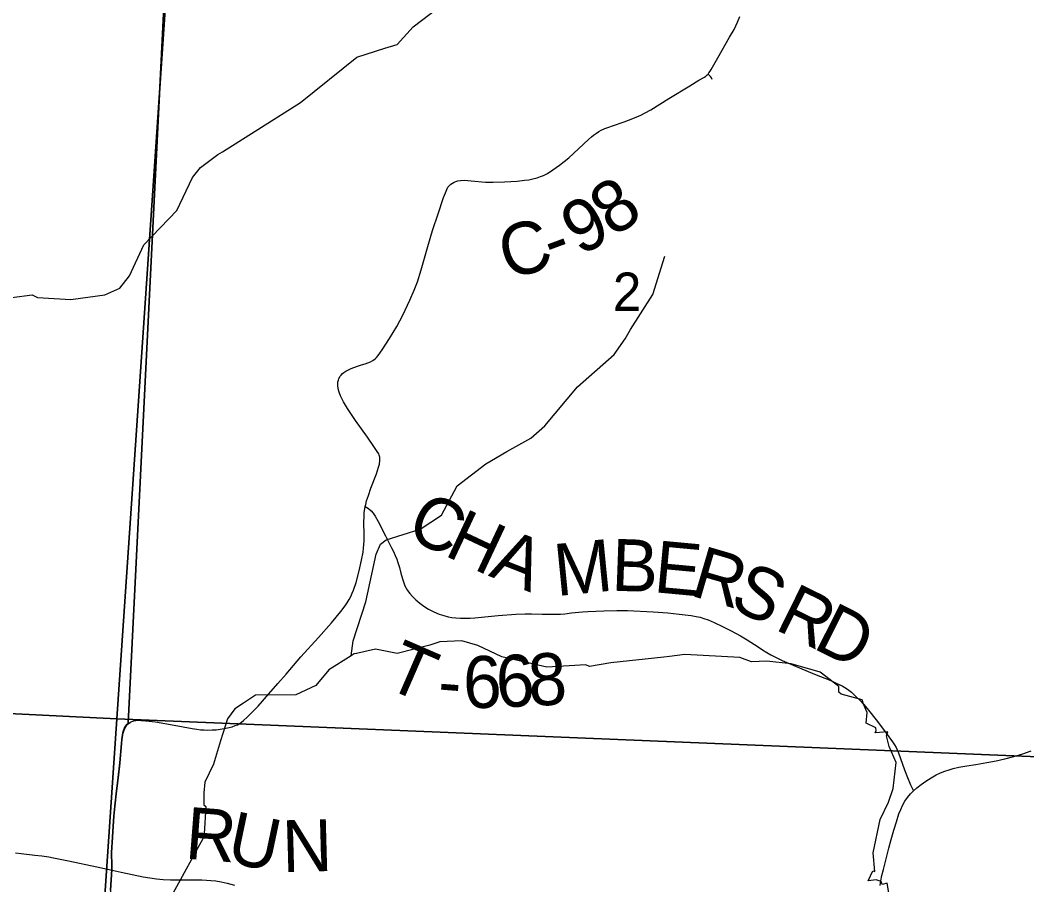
# Model space of a CAD drawing. Extents: x 396.2 to 468.4, y 232.6 to 279.1.
# Drawn here: x 420.393 to 421.493, y 271.098 to 272.044 of the extents above; entities that cross this region are included whole.
import ezdxf

# ---------------------------------------------------------------- set-up
doc = ezdxf.new("R2010")
doc.units = 0
for name, color, linetype in [('GM_X_County_Road', 7, 'Continuous'), ('GM_X_County_Road_Text', 7, 'Continuous'), ('GM_X_Minor_River', 7, 'Continuous'), ('GM_X_Section', 7, 'Continuous'), ('GM_X_Section_Text', 7, 'Continuous'), ('GM_X_Township', 7, 'Continuous'), ('GM_X_Township_Road', 7, 'Continuous'), ('GM_X_Township_Road_Text', 7, 'Continuous')]:
    doc.layers.add(name, color=color, linetype=linetype)

msp = doc.modelspace()

# ---------------------------------------------------------------- linework, layer by layer
at = {"layer": 'GM_X_County_Road'}
for points in [[(420.511, 271.2746), (420.512, 271.2754), (420.5135, 271.2763), (420.515, 271.2771), (420.517, 271.2777), (420.5195, 271.2781), (420.522, 271.2784), (420.5253, 271.2783), (420.5301, 271.2779), (420.5407, 271.2766), (420.5612, 271.273), (420.5809, 271.2693), (420.5859, 271.2686), (420.59, 271.2681), (420.5942, 271.2678), (420.5981, 271.2677), (420.6027, 271.2678), (420.6073, 271.2681), (420.6116, 271.2686), (420.616, 271.2693), (420.6214, 271.2705), (420.6245, 271.2713), (420.628, 271.2726), (420.6303, 271.2735), (420.6322, 271.2745), (420.6348, 271.2762), (420.6372, 271.278), (420.6409, 271.2817), (420.6529, 271.294), (420.6649, 271.3072), (420.6746, 271.3185), (420.6835, 271.3287), (420.6997, 271.3476), (420.719, 271.3688), (420.7334, 271.3851), (420.7435, 271.3974), (420.7481, 271.4035), (420.7505, 271.4068), (420.7526, 271.4105), (420.7544, 271.4138), (420.7559, 271.4173), (420.7573, 271.4206), (420.7601, 271.4289), (420.7636, 271.4419), (420.7661, 271.4533), (420.7678, 271.4623), (420.7684, 271.4666), (420.7687, 271.4706), (420.7688, 271.4747), (420.7689, 271.4822), (420.7687, 271.4944), (420.7689, 271.5019), (420.7691, 271.5055), (420.7696, 271.5097), (420.7702, 271.5122), (420.7706, 271.5145), (420.7716, 271.5183), (420.7736, 271.5243), (420.7764, 271.5321), (420.7823, 271.5479), (420.7847, 271.5551), (420.7856, 271.5585), (420.7861, 271.5624), (420.7859, 271.566), (420.7855, 271.5681), (420.7849, 271.5696), (420.7833, 271.5724), (420.7803, 271.5768), (420.7725, 271.5879), (420.7595, 271.6063), (420.7507, 271.6192), (420.7464, 271.6266), (420.743, 271.6333), (420.7416, 271.6371), (420.7406, 271.6407), (420.7401, 271.6448), (420.7403, 271.6483), (420.7409, 271.6504), (420.7413, 271.6518), (420.7424, 271.6541), (420.7437, 271.6559), (420.7454, 271.6576), (420.7469, 271.6588), (420.7488, 271.6602), (420.7519, 271.6617), (420.7548, 271.6629), (420.7615, 271.6655), (420.7661, 271.667), (420.7702, 271.6683), (420.7728, 271.6692), (420.7758, 271.6704), (420.7786, 271.6718), (420.7809, 271.6735), (420.7826, 271.6752), (420.7843, 271.6772), (420.7887, 271.6834), (420.7968, 271.6959), (420.8045, 271.7091), (420.8112, 271.7214), (420.819, 271.7377), (420.8235, 271.7486), (420.8272, 271.7578), (420.8313, 271.7708), (420.8392, 271.7989), (420.8437, 271.814), (420.8499, 271.8322), (420.8558, 271.8499), (420.8578, 271.8552), (420.8592, 271.8588), (420.8606, 271.8614), (420.8618, 271.8628), (420.8626, 271.8636), (420.8638, 271.8646), (420.8656, 271.8658), (420.8674, 271.8668), (420.8691, 271.8675), (420.8712, 271.8681), (420.8743, 271.8686), (420.8788, 271.8689), (420.8861, 271.8683), (420.9015, 271.8668), (420.9059, 271.8666), (420.91, 271.8666), (420.9224, 271.8671), (420.9363, 271.868), (420.9444, 271.8688), (420.9488, 271.8694), (420.9535, 271.8704), (420.958, 271.8716), (420.9616, 271.8729), (420.9649, 271.8742), (420.9693, 271.8764), (420.9753, 271.8801), (420.9824, 271.8853), (420.9926, 271.8935), (421.0141, 271.9133), (421.0176, 271.9163), (421.0198, 271.918), (421.0229, 271.9204), (421.0254, 271.9221), (421.0282, 271.9235), (421.0321, 271.9253), (421.0364, 271.9269), (421.0403, 271.9283), (421.0531, 271.9327), (421.0579, 271.9345), (421.0627, 271.9363), (421.067, 271.9381), (421.0714, 271.9401), (421.0762, 271.9425), (421.0822, 271.9459), (421.1022, 271.9581), (421.1251, 271.972), (421.135, 271.9783), (421.1409, 271.9817), (421.1424, 271.9828), (421.1438, 271.984), (421.1449, 271.985), (421.1459, 271.9864), (421.1471, 271.9881), (421.1483, 271.9898), (421.1555, 272.0028), (421.1685, 272.0252), (421.1733, 272.0335), (421.1754, 272.0375), (421.1772, 272.0415), (421.1797, 272.0478)], [(420.4933, 271.1146), (420.4933, 271.1188), (420.4931, 271.1333), (420.4939, 271.1503), (420.4946, 271.1621), (420.4955, 271.1732), (420.4965, 271.1841), (420.4984, 271.2008), (420.5002, 271.2155), (420.5021, 271.2314), (420.5038, 271.2524), (420.5043, 271.2569), (420.5049, 271.2616), (420.5054, 271.2642), (420.5061, 271.2666), (420.5073, 271.2695), (420.5087, 271.2718), (420.51, 271.2736), (420.511, 271.2746)], [(421.3331, 271.0976), (421.3339, 271.1028), (421.335, 271.1087), (421.3366, 271.1152), (421.3426, 271.1386), (421.3452, 271.1482), (421.348, 271.1581), (421.3508, 271.1673), (421.3536, 271.176), (421.3555, 271.181), (421.3574, 271.1853), (421.36, 271.1898), (421.3628, 271.1939), (421.3662, 271.1981), (421.3694, 271.2014), (421.3731, 271.2046), (421.3778, 271.2081), (421.383, 271.2117), (421.3889, 271.2155), (421.3944, 271.2186), (421.3991, 271.2209), (421.4037, 271.2228), (421.4084, 271.2244), (421.413, 271.2258), (421.419, 271.2271), (421.4279, 271.2287), (421.4376, 271.2302), (421.4497, 271.2321), (421.4598, 271.234), (421.4695, 271.2363), (421.4793, 271.2388), (421.4889, 271.2417), (421.4982, 271.245)], [(420.3879, 271.1335), (420.3938, 271.1328), (420.4089, 271.1311), (420.4167, 271.1302), (420.4241, 271.129), (420.4293, 271.1281), (420.4456, 271.1249), (420.4766, 271.1182), (420.4933, 271.1146)], [(420.4933, 271.1146), (420.5032, 271.1125), (420.5273, 271.1074), (420.5348, 271.106), (420.5418, 271.105), (420.5492, 271.1043), (420.5574, 271.1039), (420.5718, 271.1038), (420.5916, 271.1038), (420.5966, 271.1036), (420.6015, 271.1033), (420.6068, 271.1027), (420.6125, 271.1018), (420.6191, 271.1003), (420.6273, 271.098)]]:
    msp.add_lwpolyline(points, dxfattribs=at)
at = {"layer": 'GM_X_Minor_River'}
for points in [[(420.3836, 271.7405), (420.406, 271.7435), (420.412, 271.7407), (420.4482, 271.7384), (420.4854, 271.7437), (420.5018, 271.7507), (420.5125, 271.7644), (420.5282, 271.7981), (420.5641, 271.8357), (420.5811, 271.872), (420.5901, 271.8827), (420.6091, 271.8969), (420.6141, 271.8998), (420.6992, 271.9537), (420.7608, 272.0034), (420.7914, 272.0134), (420.8051, 272.0172), (420.8227, 272.0367), (420.8575, 272.0633)], [(420.7546, 271.3489), (420.7571, 271.3654), (420.7708, 271.4079), (420.7819, 271.46), (420.7867, 271.4708), (420.7929, 271.4756), (420.8303, 271.4873), (420.8535, 271.5025), (420.8707, 271.5346), (420.902, 271.5587), (420.9251, 271.5724), (420.9512, 271.5867), (420.9664, 271.6003), (421.0021, 271.6428), (421.0421, 271.6784), (421.0543, 271.6955), (421.0603, 271.7055), (421.0845, 271.7439), (421.0975, 271.786)], [(420.9687, 271.3364), (420.9195, 271.3477), (420.8931, 271.3602), (420.8757, 271.3651), (420.8518, 271.3643), (420.8409, 271.3605), (420.805, 271.3516), (420.7815, 271.3562), (420.7605, 271.3513)], [(420.7608, 271.3514), (420.7581, 271.3512), (420.7547, 271.3489), (420.7305, 271.3336), (420.7162, 271.3165), (420.6942, 271.3061)], [(421.3408, 271.1003), (421.3352, 271.0989), (421.3341, 271.102), (421.3288, 271.1039), (421.3201, 271.1027), (421.325, 271.1137), (421.3273, 271.113), (421.3254, 271.1335), (421.3329, 271.17), (421.342, 271.189), (421.3472, 271.2039), (421.3506, 271.2324), (421.343, 271.2499), (421.34, 271.2613), (421.3415, 271.2658), (421.3275, 271.2647), (421.3286, 271.2673), (421.3283, 271.27), (421.3177, 271.2753), (421.3188, 271.2871), (421.315, 271.2962), (421.3135, 271.3007), (421.2904, 271.3071), (421.2878, 271.309), (421.2878, 271.3155), (421.2673, 271.331), (421.2356, 271.3401), (421.2091, 271.3431), (421.1925, 271.3423), (421.1796, 271.3472), (421.1195, 271.3505), (421.1029, 271.3482), (421.0964, 271.3474), (421.0386, 271.3412), (421.0152, 271.3373), (421.0114, 271.3392), (420.9687, 271.3364)], [(420.6942, 271.3061), (420.65, 271.3057), (420.6372, 271.2973), (420.6274, 271.2908), (420.6194, 271.2801), (420.6119, 271.2558), (420.6044, 271.2303), (420.5946, 271.2109), (420.5938, 271.1991), (420.5935, 271.196), (420.5935, 271.1858), (420.5957, 271.1843), (420.5939, 271.1542), (420.5928, 271.1497)], [(420.5928, 271.1497), (420.5599, 271.0891)], [(421.6646, 270.6998), (421.6555, 270.7184), (421.6407, 270.7385), (421.596, 270.7814), (421.5866, 270.7886), (421.5401, 270.7964), (421.5363, 270.7964), (421.4796, 270.8134), (421.4512, 270.8301), (421.4293, 270.8494), (421.4024, 270.8934), (421.3861, 270.9132), (421.3861, 270.9173), (421.355, 270.969), (421.3444, 270.9895), (421.3448, 271.029), (421.3481, 271.0598), (421.3443, 271.0788), (421.3408, 271.1003)]]:
    msp.add_lwpolyline(points, dxfattribs=at)
at = {"layer": 'GM_X_Section'}
for points in [[(419.5162, 272.3211), (420.0191, 272.3027), (420.5671, 272.2854), (420.4987, 271.28), (419.4571, 271.3312), (419.4827, 271.7399), (419.5072, 272.1445)], [(420.5671, 272.2854), (421.6151, 272.2373), (421.5983, 271.983), (421.5809, 271.7277), (421.5654, 271.4805), (421.55, 271.2368), (420.4987, 271.28)], [(419.4571, 271.3312), (420.4987, 271.28), (420.43, 270.2709), (419.3993, 270.3259)], [(420.4987, 271.28), (421.55, 271.2368), (421.5332, 270.9795), (421.5171, 270.7352), (421.5012, 270.4826), (421.4857, 270.2238), (420.43, 270.2709)]]:
    msp.add_lwpolyline(points, close=True, dxfattribs=at)
at = {"layer": 'GM_X_Township'}
for points in [[(420.561, 272.2781), (420.5108, 271.2751), (420.5106, 271.2749), (420.5098, 271.2741), (420.5085, 271.2723), (420.5071, 271.27), (420.5059, 271.2671), (420.5052, 271.2647), (420.5047, 271.2622), (420.5041, 271.2574), (420.5036, 271.2529), (420.5019, 271.2319), (420.5, 271.216), (420.4982, 271.2013), (420.4963, 271.1846), (420.4953, 271.1737), (420.4944, 271.1626), (420.4937, 271.1508), (420.4929, 271.1338), (420.4931, 271.1193), (420.4931, 271.1152), (420.4917, 271.0928), (420.4241, 270.2645), (419.658, 270.3039)], [(420.4917, 271.0928), (420.4931, 271.1152), (420.4931, 271.1193), (420.4929, 271.1338), (420.4937, 271.1508), (420.4944, 271.1626), (420.4953, 271.1737), (420.4963, 271.1846), (420.4982, 271.2013), (420.5, 271.216), (420.5019, 271.2319), (420.5036, 271.2529), (420.5041, 271.2574), (420.5047, 271.2622), (420.5052, 271.2647), (420.5059, 271.2671), (420.5071, 271.27), (420.5085, 271.2723), (420.5098, 271.2741), (420.5106, 271.2749), (420.5108, 271.2751), (420.561, 272.2781)]]:
    msp.add_lwpolyline(points, dxfattribs=at)
at = {"layer": 'GM_X_Township_Road'}
for points in [[(421.1495, 271.9789), (421.1485, 271.9807), (421.1474, 271.9822), (421.1462, 271.9837), (421.1449, 271.985)], [(420.7702, 271.5122), (420.7737, 271.51), (420.7765, 271.5075), (420.7789, 271.5047), (420.7811, 271.5015), (420.7844, 271.4958), (420.7922, 271.4802), (420.7989, 271.4671), (420.801, 271.4628), (420.8029, 271.4585), (420.8045, 271.4546), (420.8059, 271.4508), (420.8075, 271.4456), (420.8092, 271.4392), (420.8107, 271.4331), (420.8122, 271.4286), (420.8135, 271.4255), (420.8147, 271.4229), (420.8164, 271.4202), (420.8187, 271.4172), (420.8217, 271.4137), (420.8254, 271.41), (420.8297, 271.4064), (420.8342, 271.4031), (420.8394, 271.3998), (420.845, 271.397), (420.851, 271.3945), (420.8559, 271.3929), (420.8607, 271.3916), (420.8649, 271.3908), (420.8693, 271.3903), (420.8743, 271.3901), (420.8794, 271.39), (420.8849, 271.3902), (420.8899, 271.3905), (420.9156, 271.3929), (420.9347, 271.3944), (420.9449, 271.3948), (420.9518, 271.3949), (420.9636, 271.3946), (420.9727, 271.3944), (420.9785, 271.3944), (420.9835, 271.3946), (420.9884, 271.3949), (420.9956, 271.3958), (421.0078, 271.3969), (421.0134, 271.3973), (421.0308, 271.3981), (421.0451, 271.3984), (421.0568, 271.3983), (421.0849, 271.3969), (421.1009, 271.3958), (421.1134, 271.3944), (421.1264, 271.3928), (421.132, 271.3918), (421.1362, 271.391), (421.1404, 271.3898), (421.1452, 271.3881), (421.1517, 271.3853), (421.1607, 271.3811), (421.1701, 271.3763), (421.1804, 271.3706), (421.1878, 271.3662), (421.1997, 271.3586), (421.2044, 271.3556), (421.2091, 271.3526), (421.2134, 271.3501), (421.2194, 271.3469), (421.2261, 271.3437), (421.2381, 271.3385), (421.2614, 271.329), (421.2791, 271.3219), (421.2857, 271.3188), (421.2914, 271.316), (421.2944, 271.3143), (421.2973, 271.3124), (421.3016, 271.309), (421.3062, 271.3049), (421.3111, 271.3001), (421.3149, 271.2959), (421.3188, 271.2912), (421.33, 271.2772), (421.3398, 271.2643), (421.3466, 271.2549), (421.3487, 271.2516), (421.3504, 271.2488), (421.3518, 271.2461), (421.3531, 271.2428), (421.3597, 271.2243), (421.3629, 271.2158), (421.3663, 271.208), (421.3694, 271.2014)]]:
    msp.add_lwpolyline(points, dxfattribs=at)

# ---------------------------------------------------------------- texts
at = {"layer": 'GM_X_County_Road_Text'}
for s, rotation, p in [('8', 34.5343, (421.0414, 271.8057)), ('9', 28.05, (421.0046, 271.7856)), ('C', 16.0435, (420.9258, 271.7597)), ('-', 20.2663, (420.975, 271.774)), ('R', 355.5284, (420.5722, 271.1272)), ('U', 348.12, (420.6168, 271.1238)), ('N', 1.5663, (420.6799, 271.1122))]:
    msp.add_text(s, height=0.0568, rotation=rotation, dxfattribs=at).set_placement(p)
at = {"layer": 'GM_X_Section_Text'}
msp.add_text('2', height=0.0419, rotation=0, dxfattribs=at).set_placement((421.0408, 271.726))
at = {"layer": 'GM_X_Township_Road_Text'}
for s, rotation, p in [('C', 334.8489, (420.8128, 271.4792)), ('H', 334.8614, (420.8551, 271.4593)), ('A', 338.441, (420.9039, 271.4366)), ('M', 5.6603, (420.9793, 271.4141)), ('B', 357.9564, (421.0387, 271.4202)), ('E', 354.6762, (421.0845, 271.4186)), ('R', 343.6638, (421.124, 271.4152)), ('S', 334.1447, (421.1664, 271.4029)), ('R', 333.7073, (421.2165, 271.3785)), ('D', 333.2509, (421.2582, 271.3579)), ('T', 336.4666, (420.7894, 271.3155)), ('6', 1.1802, (420.8776, 271.2915)), ('6', 2.5747, (420.9141, 271.2923)), ('8', 2.9936, (420.9496, 271.2939)), ('-', 355.5144, (420.8482, 271.2935))]:
    msp.add_text(s, height=0.0568, rotation=rotation, dxfattribs=at).set_placement(p)

doc.saveas('drawing.dxf')
